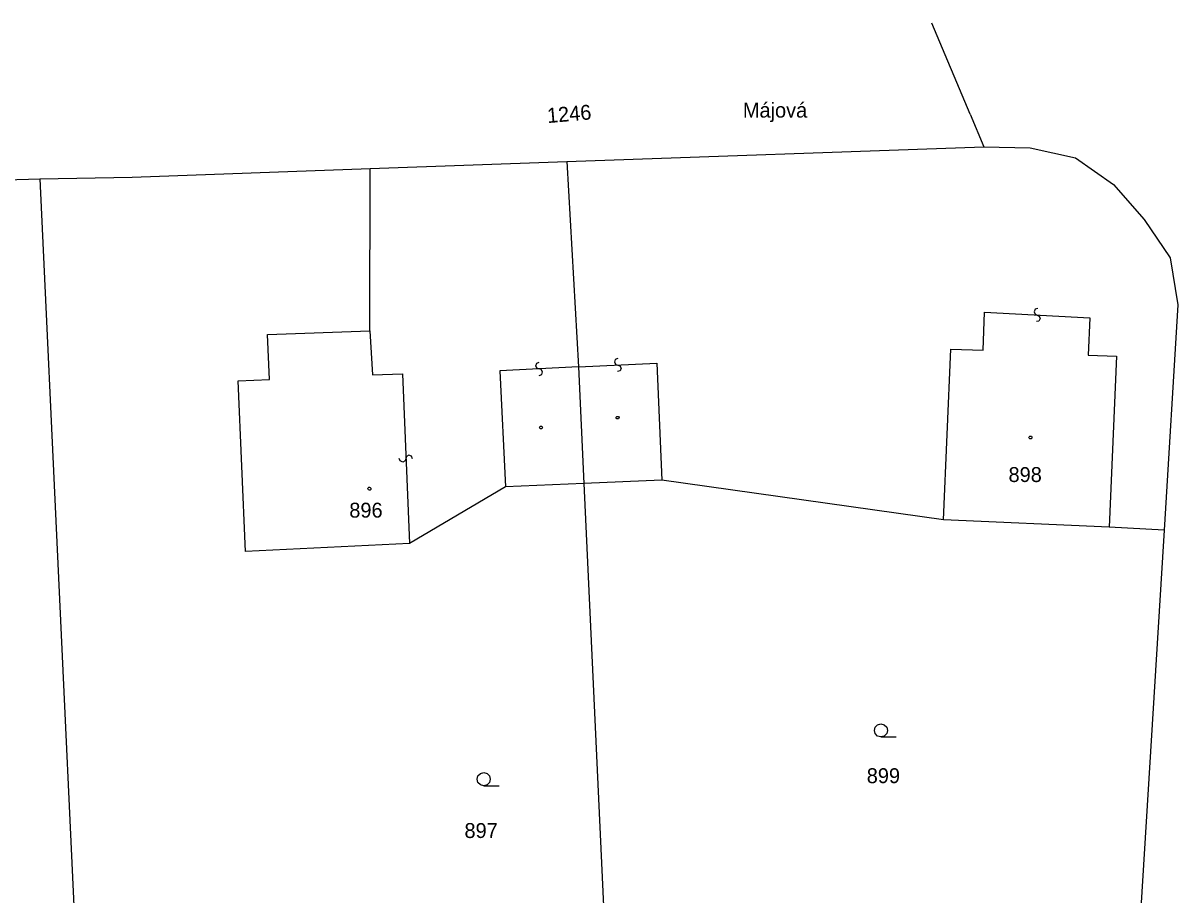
# Model space of a CAD drawing. Extents: x -456675 to -456278, y -1112395 to -1112217.
# Drawn here: x -456625.5 to -456559.7, y -1112266.7 to -1112217 of the extents above; entities that cross this region are included whole.
import ezdxf

# ---------------------------------------------------------------- set-up
doc = ezdxf.new("R2010")
doc.units = 0
doc.layers.add('Katastralni_mapa', color=7, linetype='Continuous')

msp = doc.modelspace()

# ---------------------------------------------------------------- linework, layer by layer
at = {"layer": 'Katastralni_mapa'}
for points in [[(-456571.48, -1112222.19), (-456573.674, -1112216.993)], [(-456571.48, -1112222.19), (-456570.71, -1112224.04)], [(-456594.48, -1112224.88), (-456570.71, -1112224.04)], [(-456570.71, -1112224.04), (-456568.07, -1112224.1)], [(-456568.07, -1112224.1), (-456565.48, -1112224.67)], [(-456605.68, -1112225.29), (-456594.48, -1112224.88)], [(-456594.48, -1112224.88), (-456593.8, -1112236.6)], [(-456565.48, -1112224.67), (-456563.32, -1112226.19)], [(-456619.24, -1112225.77), (-456605.68, -1112225.29)], [(-456605.69, -1112234.54), (-456605.68, -1112225.29)], [(-456643.44, -1112226.42), (-456624.5, -1112225.87)], [(-456624.5, -1112225.87), (-456619.24, -1112225.77)], [(-456624.5, -1112225.87), (-456622.42, -1112270.58)], [(-456563.32, -1112226.19), (-456561.57, -1112228.19)], [(-456561.57, -1112228.19), (-456560.09, -1112230.38)], [(-456560.09, -1112230.38), (-456559.65, -1112233.05)], [(-456567.625, -1112233.267), (-456567.778, -1112233.309), (-456567.846, -1112233.461), (-456567.783, -1112233.599), (-456567.548, -1112233.697), (-456567.495, -1112233.839), (-456567.573, -1112233.981), (-456567.715, -1112234.013)], [(-456559.65, -1112233.05), (-456560.44, -1112245.9)], [(-456570.74, -1112235.64), (-456570.68, -1112233.48)], [(-456570.68, -1112233.48), (-456564.66, -1112233.8)], [(-456564.66, -1112233.8), (-456564.77, -1112235.92)], [(-456611.52, -1112234.74), (-456605.69, -1112234.54)], [(-456611.42, -1112237.32), (-456611.52, -1112234.74)], [(-456605.69, -1112234.54), (-456605.54, -1112237.04)], [(-456573, -1112245.31), (-456572.59, -1112235.58)], [(-456572.59, -1112235.58), (-456570.74, -1112235.64)], [(-456564.77, -1112235.92), (-456563.15, -1112235.99)], [(-456563.15, -1112235.99), (-456563.57, -1112245.73)], [(-456593.8, -1112236.6), (-456598.29, -1112236.82)], [(-456596.052, -1112237.086), (-456595.904, -1112237.028), (-456595.852, -1112236.871), (-456595.928, -1112236.739), (-456596.172, -1112236.666), (-456596.239, -1112236.529), (-456596.176, -1112236.381), (-456596.038, -1112236.334)], [(-456593.8, -1112236.6), (-456589.34, -1112236.38)], [(-456593.8, -1112236.6), (-456593.5, -1112243.25)], [(-456591.564, -1112236.114), (-456591.711, -1112236.172), (-456591.763, -1112236.329), (-456591.687, -1112236.461), (-456591.443, -1112236.534), (-456591.376, -1112236.671), (-456591.439, -1112236.819), (-456591.576, -1112236.866)], [(-456589.34, -1112236.38), (-456589.05, -1112243.06)], [(-456613.2, -1112237.4), (-456611.42, -1112237.32)], [(-456612.79, -1112247.13), (-456613.2, -1112237.4)], [(-456605.54, -1112237.04), (-456603.84, -1112237)], [(-456603.84, -1112237), (-456603.44, -1112246.66)], [(-456598.29, -1112236.82), (-456597.97, -1112243.44)], [(-456603.264, -1112241.84), (-456603.32, -1112241.692), (-456603.478, -1112241.638), (-456603.61, -1112241.714), (-456603.685, -1112241.957), (-456603.822, -1112242.023), (-456603.97, -1112241.959), (-456604.016, -1112241.82)], [(-456593.5, -1112243.25), (-456597.97, -1112243.44)], [(-456589.05, -1112243.06), (-456593.5, -1112243.25)], [(-456593.5, -1112243.25), (-456592.28, -1112269.37)], [(-456573, -1112245.31), (-456589.05, -1112243.06)], [(-456597.97, -1112243.44), (-456603.44, -1112246.66)], [(-456563.57, -1112245.73), (-456573, -1112245.31)], [(-456560.44, -1112245.9), (-456563.57, -1112245.73)], [(-456560.44, -1112245.9), (-456561.8, -1112268.06)], [(-456603.44, -1112246.66), (-456612.79, -1112247.13)], [(-456576.57, -1112257.697), (-456576.76, -1112257.647), (-456576.895, -1112257.507), (-456576.945, -1112257.322), (-456576.895, -1112257.137), (-456576.76, -1112256.997), (-456576.57, -1112256.947), (-456576.38, -1112256.997), (-456576.245, -1112257.137), (-456576.195, -1112257.322), (-456576.245, -1112257.507), (-456576.38, -1112257.647), (-456576.57, -1112257.697), (-456575.695, -1112257.697)], [(-456599.21, -1112260.475), (-456599.4, -1112260.425), (-456599.535, -1112260.285), (-456599.585, -1112260.1), (-456599.535, -1112259.915), (-456599.4, -1112259.775), (-456599.21, -1112259.725), (-456599.02, -1112259.775), (-456598.885, -1112259.915), (-456598.835, -1112260.1), (-456598.885, -1112260.285), (-456599.02, -1112260.425), (-456599.21, -1112260.475), (-456598.335, -1112260.475)]]:
    msp.add_lwpolyline(points, dxfattribs=at)
for points in [[(-456595.895, -1112239.975), (-456595.85, -1112240.05), (-456595.895, -1112240.125), (-456595.985, -1112240.125), (-456596.03, -1112240.05), (-456595.985, -1112239.975)], [(-456591.535, -1112239.415), (-456591.49, -1112239.49), (-456591.535, -1112239.565), (-456591.625, -1112239.565), (-456591.67, -1112239.49), (-456591.625, -1112239.415)], [(-456568.051, -1112240.537), (-456568.001, -1112240.547), (-456567.976, -1112240.592), (-456567.966, -1112240.622), (-456567.976, -1112240.667), (-456568.016, -1112240.702), (-456568.051, -1112240.707), (-456568.096, -1112240.692), (-456568.126, -1112240.662), (-456568.136, -1112240.622), (-456568.126, -1112240.577), (-456568.086, -1112240.542)], [(-456605.722, -1112243.458), (-456605.672, -1112243.468), (-456605.647, -1112243.513), (-456605.637, -1112243.543), (-456605.647, -1112243.588), (-456605.687, -1112243.623), (-456605.722, -1112243.628), (-456605.767, -1112243.613), (-456605.797, -1112243.583), (-456605.807, -1112243.543), (-456605.797, -1112243.498), (-456605.757, -1112243.463)]]:
    msp.add_lwpolyline(points, close=True, dxfattribs=at)

# ---------------------------------------------------------------- texts
msp.add_text('1246', height=0.85, rotation=4.92744, dxfattribs=at).set_placement((-456595.563, -1112222.697))
for s, p in [('Májová', (-456584.44, -1112222.383)), ('898', (-456569.301, -1112243.16)), ('896', (-456606.866, -1112245.19)), ('899', (-456577.38, -1112260.33)), ('897', (-456600.304, -1112263.457))]:
    msp.add_text(s, height=0.85, dxfattribs=at).set_placement(p)

doc.saveas('drawing.dxf')
